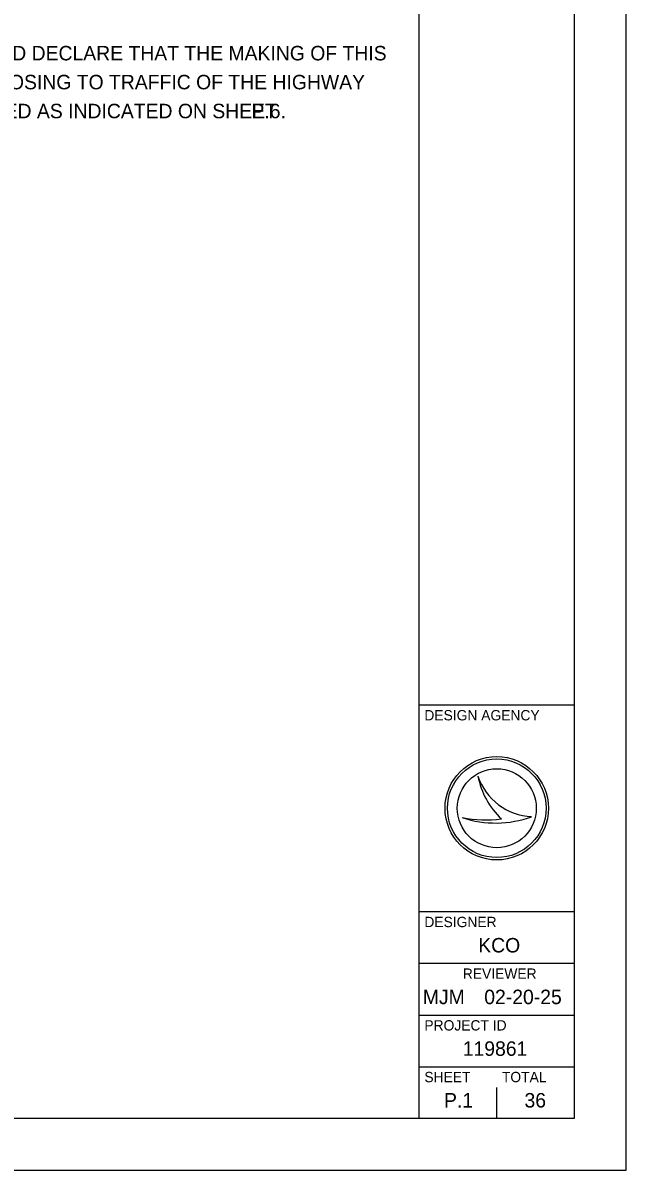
# Model space of a CAD drawing. Extents: x 0 to 34, y 0 to 22.
# Drawn here: x 28.17 to 34, y 0 to 11.1 of the extents above; entities that cross this region are included whole.
import ezdxf

# ---------------------------------------------------------------- set-up
doc = ezdxf.new("R2010")
doc.units = 0
for name, color, linetype in [('SH_Border', 7, 'Continuous'), ('SH_Cut_Line', 7, 'Continuous'), ('SH_Data', 7, 'Continuous')]:
    doc.layers.add(name, color=color, linetype=linetype)

msp = doc.modelspace()

# ---------------------------------------------------------------- linework, layer by layer
at = {"layer": 'SH_Border'}
for p, q in [((32, 0.5), (32, 21.5)), ((32, 4.5), (33.5, 4.5)), ((32, 2.5), (33.5, 2.5)), ((32, 2), (33.5, 2)), ((32, 1.5), (33.5, 1.5)), ((32, 1), (33.5, 1))]:
    msp.add_line(p, q, dxfattribs=at)
msp.add_lwpolyline([(1.5, 21.5), (33.5, 21.5), (33.5, 0.5), (1.5, 0.5)], close=True, dxfattribs=at)
at = {"layer": 'SH_Cut_Line'}
msp.add_lwpolyline([(0, 0), (34, 0), (34, 22), (0, 22)], close=True, dxfattribs=at)
at = {"layer": 'SH_Data'}
for p, q in [((32.567, 3.81), (32.567, 3.81)), ((32.75, 3.5), (32.75, 3.5)), ((32.417, 3.41), (32.417, 3.41)), ((33.087, 3.419), (33.087, 3.419)), ((32.75, 0.5), (32.75, 0.8)), ((32.375, 0.675), (32.375, 0.675))]:
    msp.add_line(p, q, dxfattribs=at)
for radius in [0.5, 0.477, 0.477, 0.382]:
    msp.add_circle((32.75, 3.5), radius, dxfattribs=at)
for centre, radius, start, end in [((33.116, 3.998), 0.58, 198.9257, 198.9319), ((33.347, 3.97), 0.796, 191.6379, 191.6421), ((33.116, 3.998), 0.58, 198.9319, 267.1657), ((33.347, 3.97), 0.796, 191.6421, 226.0947), ((32.739, 4.37), 1.013, 251.4576, 290.0832), ((32.648, 4.654), 1.266, 259.4964, 259.4995), ((32.739, 4.37), 1.013, 251.4527, 251.4576), ((32.648, 4.654), 1.266, 259.4995, 276.6672)]:
    msp.add_arc(centre, radius, start, end, dxfattribs=at)

# ---------------------------------------------------------------- texts
for s, height, p in [(' I HEREBY APPROVE THESE PLANS AND DECLARE THAT THE MAKING OF THIS', 0.14, (24.528, 10.735)), ('IMPROVEMENT WILL REQUIRE THE CLOSING TO TRAFFIC OF THE HIGHWAY', 0.14, (24.528, 10.455)), ('AND THAT DETOURS WILL BE PROVIDED AS INDICATED ON SHEET ', 0.14, (24.528, 10.175)), ('P.6', 0.14, (30.378, 10.175)), ('.', 0.14, (30.66, 10.175)), ('DESIGN AGENCY', 0.1, (32.05, 4.35)), ('DESIGNER', 0.1, (32.05, 2.35)), ('KCO', 0.14, (32.571, 2.105)), ('REVIEWER', 0.1, (32.422, 1.85)), ('MJM', 0.14, (32.035, 1.605)), ('02-20-25', 0.14, (32.629, 1.605)), ('PROJECT ID', 0.1, (32.05, 1.35)), ('119861', 0.14, (32.421, 1.105)), ('SHEET', 0.1, (32.05, 0.85)), ('TOTAL', 0.1, (32.8, 0.85)), ('P.1', 0.14, (32.24, 0.605)), ('36', 0.14, (33.018, 0.605))]:
    msp.add_text(s, height=height, dxfattribs=at).set_placement(p)

doc.saveas('drawing.dxf')
